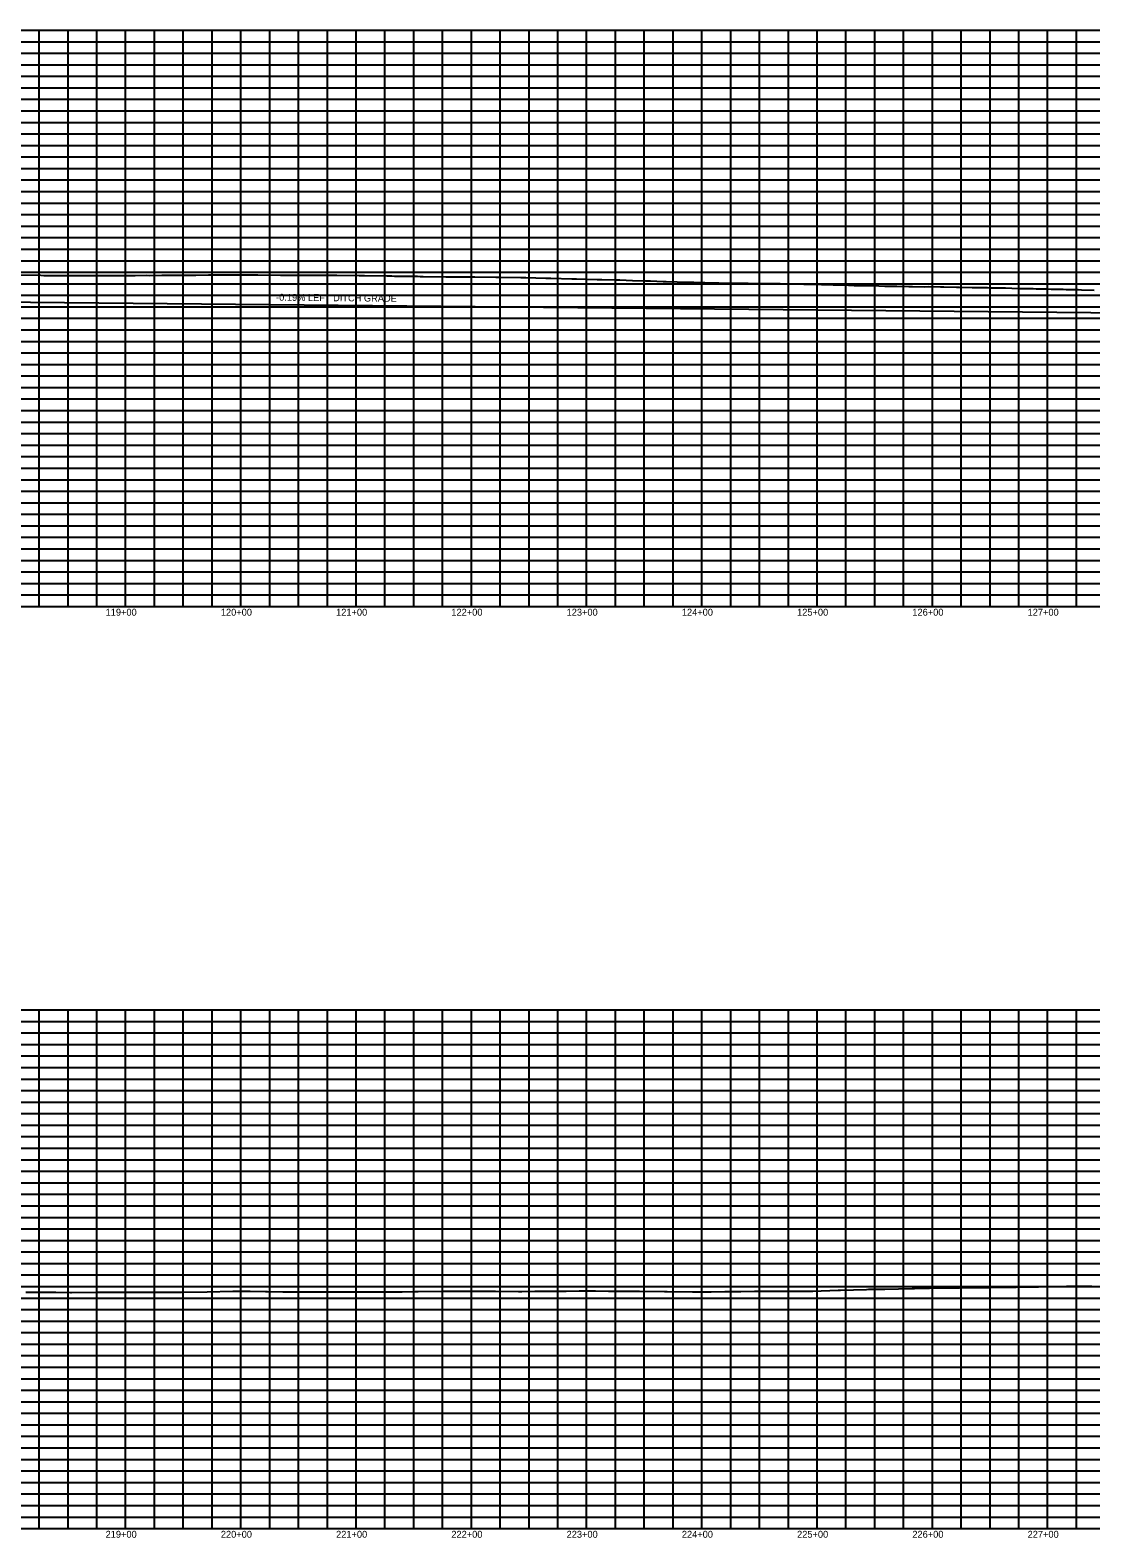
# Model space of a CAD drawing. Extents: x 1399671 to 1408349, y 1930471 to 1933387.
# Drawn here: x 1402141 to 1403062, y 1932071 to 1933379 of the extents above; entities that cross this region are included whole.
import ezdxf

# ---------------------------------------------------------------- set-up
doc = ezdxf.new("R2010")
doc.units = 0
for name, color, linetype in [('R_Exist Surface', 7, 'Continuous'), ('R_Grid', 7, 'Continuous'), ('R_Grid Annot', 7, 'Continuous'), ('R_Vert Alg', 7, 'Continuous'), ('R_Vert Alg Annot', 7, 'Continuous')]:
    doc.layers.add(name, color=color, linetype=linetype)

msp = doc.modelspace()

# ---------------------------------------------------------------- linework, layer by layer
at = {"layer": 'R_Exist Surface'}
for points in [[(1402131.6, 1933166.2), (1402150.7, 1933166.1), (1402153.1, 1933165.8), (1402164.1, 1933165.8), (1402166.5, 1933165.8), (1402177.4, 1933165.7), (1402179.8, 1933165.7), (1402190.8, 1933165.7), (1402193.2, 1933165.7), (1402195.6, 1933165.6), (1402206.5, 1933165.6), (1402216.9, 1933165.7), (1402219.5, 1933165.7), (1402229.8, 1933165.8), (1402232.4, 1933165.8), (1402242.7, 1933165.9), (1402245.3, 1933165.8), (1402255.6, 1933165.9), (1402258.2, 1933165.9), (1402269.3, 1933166), (1402271.7, 1933166), (1402282.7, 1933166.1), (1402285.1, 1933166.1), (1402296.2, 1933166.2), (1402298.6, 1933166.2), (1402309.7, 1933166.3), (1402312.1, 1933166.3), (1402314.5, 1933166.2), (1402334.1, 1933166.2), (1402336.5, 1933166.2), (1402338.8, 1933166.2), (1402358.6, 1933166.1), (1402360.9, 1933166.1), (1402380.3, 1933166), (1402384.2, 1933166.1), (1402388.4, 1933166.1), (1402407.5, 1933166), (1402426.8, 1933165.8), (1402431.3, 1933165.7), (1402450.7, 1933165.5), (1402455.1, 1933165.4), (1402457.5, 1933165.3), (1402477.4, 1933165.1), (1402479.8, 1933165), (1402482.4, 1933164.9), (1402502, 1933164.7), (1402504.6, 1933164.6), (1402522.7, 1933164.5), (1402527.2, 1933164.5), (1402545.5, 1933164.4), (1402549.8, 1933164.4), (1402567, 1933164), (1402571.5, 1933164), (1402588.7, 1933163.5), (1402593.1, 1933163.5), (1402611.2, 1933162.9), (1402615.3, 1933162.9), (1402633.4, 1933162.3), (1402637.4, 1933162.3), (1402648.6, 1933161.9), (1402652.9, 1933161.9), (1402664.1, 1933161.5), (1402675.3, 1933161), (1402679.5, 1933161), (1402690.7, 1933160.6), (1402693.1, 1933160.5), (1402712.4, 1933160), (1402714.8, 1933160), (1402717.3, 1933159.9), (1402736.4, 1933159.4), (1402738.9, 1933159.4), (1402749.4, 1933159.2), (1402753.8, 1933159.2), (1402764.3, 1933159), (1402774.7, 1933158.9), (1402779.2, 1933158.8), (1402789.6, 1933158.7), (1402792.2, 1933158.7), (1402812.6, 1933158.1), (1402815.1, 1933158.1), (1402817.7, 1933158.1), (1402838, 1933157.6), (1402840.6, 1933157.6), (1402851.5, 1933157.4), (1402856.3, 1933157.2), (1402867, 1933157), (1402877.7, 1933156.8), (1402882.9, 1933156.6), (1402893.4, 1933156.4), (1402903.9, 1933156.2), (1402907, 1933156.2), (1402917.6, 1933156), (1402920.5, 1933156.1), (1402931.3, 1933155.8), (1402934.1, 1933155.9), (1402945, 1933155.7), (1402947.6, 1933155.7), (1402958.6, 1933155.4), (1402961, 1933155.4), (1402971.9, 1933155.2), (1402974.3, 1933155.1), (1402985.3, 1933154.9), (1402987.6, 1933154.9), (1402998.6, 1933154.6), (1403001, 1933154.6), (1403011.5, 1933154.4), (1403014.1, 1933154.3), (1403024.5, 1933154.1), (1403027.2, 1933154), (1403037.6, 1933153.8), (1403040.3, 1933153.7), (1403050.6, 1933153.5), (1403053.5, 1933153.4), (1403064.5, 1933153.1)], [(1402137.7, 1932283.7), (1402150, 1932283.6), (1402162.4, 1932283.6), (1402163.6, 1932283.6), (1402176.2, 1932283.5), (1402177.3, 1932283.5), (1402199, 1932283.6), (1402200.7, 1932283.6), (1402222.6, 1932283.6), (1402224, 1932283.6), (1402247.9, 1932283.7), (1402248, 1932283.7), (1402248.1, 1932283.7), (1402249.6, 1932283.7), (1402272, 1932283.7), (1402272.7, 1932283.7), (1402295, 1932284.1), (1402317.2, 1932284.6), (1402318, 1932284.6), (1402331.5, 1932284.4), (1402332.2, 1932284.4), (1402345.5, 1932284.3), (1402346.4, 1932284.3), (1402347.4, 1932284.3), (1402360.6, 1932284.1), (1402361.8, 1932284.1), (1402374.8, 1932284), (1402376.1, 1932284), (1402398.4, 1932284), (1402399.7, 1932284), (1402401.1, 1932284), (1402423.3, 1932283.9), (1402424.6, 1932283.9), (1402435.9, 1932284), (1402438.7, 1932284), (1402450, 1932284.1), (1402461.2, 1932284.1), (1402464, 1932284.1), (1402475.3, 1932284.2), (1402478.1, 1932284.2), (1402498.9, 1932284.4), (1402501.6, 1932284.4), (1402522.5, 1932284.6), (1402542.6, 1932284.5), (1402545.2, 1932284.5), (1402565.2, 1932284.3), (1402568, 1932284.3), (1402579.3, 1932284.4), (1402580.8, 1932284.4), (1402592, 1932284.5), (1402593.5, 1932284.5), (1402604.8, 1932284.6), (1402606.3, 1932284.6), (1402617.6, 1932284.7), (1402619, 1932284.7), (1402630.4, 1932284.7), (1402631.8, 1932284.7), (1402643.2, 1932284.6), (1402644.6, 1932284.6), (1402656, 1932284.6), (1402657.4, 1932284.6), (1402668.8, 1932284.5), (1402670.1, 1932284.5), (1402691.8, 1932284.2), (1402694.2, 1932284.2), (1402716, 1932283.9), (1402718.3, 1932283.9), (1402729.9, 1932284), (1402731.1, 1932284), (1402732.3, 1932284), (1402744, 1932284.2), (1402745.1, 1932284.2), (1402756.8, 1932284.3), (1402758, 1932284.3), (1402769.7, 1932284.5), (1402770.9, 1932284.5), (1402782.4, 1932284.5), (1402783.6, 1932284.5), (1402795.1, 1932284.5), (1402803.1, 1932284.5), (1402806.5, 1932284.5), (1402807.8, 1932284.5), (1402819.2, 1932284.5), (1402820.5, 1932284.5), (1402842.5, 1932285.3), (1402844.6, 1932285.3), (1402866.9, 1932286.1), (1402868.8, 1932286.2), (1402880.8, 1932286.4), (1402882.8, 1932286.4), (1402894.7, 1932286.7), (1402906.6, 1932286.9), (1402908.7, 1932286.9), (1402920.6, 1932287.1), (1402921.7, 1932287.2), (1402933.5, 1932287.3), (1402934.7, 1932287.3), (1402946.4, 1932287.5), (1402947.7, 1932287.5), (1402959.4, 1932287.6), (1402960.7, 1932287.7), (1402972.3, 1932287.8), (1402974.7, 1932287.8), (1402994.4, 1932288), (1402996.9, 1932288.1), (1403016.4, 1932288.3), (1403037.9, 1932288.7), (1403040.5, 1932288.8), (1403062.3, 1932289.3)]]:
    msp.add_lwpolyline(points, dxfattribs=at)
at = {"layer": 'R_Grid'}
for p, q in [((1400324.2, 1933378.6), (1408224.2, 1933378.6)), ((1400324.2, 1933378.6), (1408224.2, 1933378.6)), ((1402149.2, 1932878.6), (1402149.2, 1933378.6)), ((1402174.2, 1932878.6), (1402174.2, 1933378.6)), ((1402199.2, 1932878.6), (1402199.2, 1933378.6)), ((1402224.2, 1932878.6), (1402224.2, 1933378.6)), ((1402249.2, 1932878.6), (1402249.2, 1933378.6)), ((1402274.2, 1932878.6), (1402274.2, 1933378.6)), ((1402299.2, 1932878.6), (1402299.2, 1933378.6)), ((1402324.2, 1932878.6), (1402324.2, 1933378.6)), ((1402349.2, 1932878.6), (1402349.2, 1933378.6)), ((1402374.2, 1932878.6), (1402374.2, 1933378.6)), ((1402399.2, 1932878.6), (1402399.2, 1933378.6)), ((1402424.2, 1932878.6), (1402424.2, 1933378.6)), ((1402449.2, 1932878.6), (1402449.2, 1933378.6)), ((1402474.2, 1932878.6), (1402474.2, 1933378.6)), ((1402499.2, 1932878.6), (1402499.2, 1933378.6)), ((1402524.2, 1932878.6), (1402524.2, 1933378.6)), ((1402549.2, 1932878.6), (1402549.2, 1933378.6)), ((1402574.2, 1932878.6), (1402574.2, 1933378.6)), ((1402599.2, 1932878.6), (1402599.2, 1933378.6)), ((1402624.2, 1932878.6), (1402624.2, 1933378.6)), ((1402649.2, 1932878.6), (1402649.2, 1933378.6)), ((1402674.2, 1932878.6), (1402674.2, 1933378.6)), ((1402699.2, 1932878.6), (1402699.2, 1933378.6)), ((1402724.2, 1932878.6), (1402724.2, 1933378.6)), ((1402749.2, 1932878.6), (1402749.2, 1933378.6)), ((1402774.2, 1932878.6), (1402774.2, 1933378.6)), ((1402799.2, 1932878.6), (1402799.2, 1933378.6)), ((1402824.2, 1932878.6), (1402824.2, 1933378.6)), ((1402849.2, 1932878.6), (1402849.2, 1933378.6)), ((1402874.2, 1932878.6), (1402874.2, 1933378.6)), ((1402899.2, 1932878.6), (1402899.2, 1933378.6)), ((1402924.2, 1932878.6), (1402924.2, 1933378.6)), ((1402949.2, 1932878.6), (1402949.2, 1933378.6)), ((1402974.2, 1932878.6), (1402974.2, 1933378.6)), ((1402999.2, 1932878.6), (1402999.2, 1933378.6)), ((1403024.2, 1932878.6), (1403024.2, 1933378.6)), ((1403049.2, 1932878.6), (1403049.2, 1933378.6)), ((1400324.2, 1933368.6), (1408224.2, 1933368.6)), ((1400324.2, 1933358.6), (1408224.2, 1933358.6)), ((1400324.2, 1933348.6), (1408224.2, 1933348.6)), ((1400324.2, 1933338.6), (1408224.2, 1933338.6)), ((1400324.2, 1933328.6), (1408224.2, 1933328.6)), ((1400324.2, 1933318.6), (1408224.2, 1933318.6)), ((1400324.2, 1933308.6), (1408224.2, 1933308.6)), ((1400324.2, 1933298.6), (1408224.2, 1933298.6)), ((1400324.2, 1933288.6), (1408224.2, 1933288.6)), ((1400324.2, 1933278.6), (1408224.2, 1933278.6)), ((1400324.2, 1933268.6), (1408224.2, 1933268.6)), ((1400324.2, 1933258.6), (1408224.2, 1933258.6)), ((1400324.2, 1933248.6), (1408224.2, 1933248.6)), ((1400324.2, 1933238.6), (1408224.2, 1933238.6)), ((1400324.2, 1933228.6), (1408224.2, 1933228.6)), ((1400324.2, 1933218.6), (1408224.2, 1933218.6)), ((1400324.2, 1933208.6), (1408224.2, 1933208.6)), ((1400324.2, 1933198.6), (1408224.2, 1933198.6)), ((1400324.2, 1933188.6), (1408224.2, 1933188.6)), ((1400324.2, 1933178.6), (1408224.2, 1933178.6)), ((1400324.2, 1933168.6), (1408224.2, 1933168.6)), ((1400324.2, 1933158.6), (1408224.2, 1933158.6)), ((1400324.2, 1933148.6), (1408224.2, 1933148.6)), ((1400324.2, 1933138.6), (1408224.2, 1933138.6)), ((1400324.2, 1933128.6), (1408224.2, 1933128.6)), ((1400324.2, 1933118.6), (1408224.2, 1933118.6)), ((1400324.2, 1933108.6), (1408224.2, 1933108.6)), ((1400324.2, 1933098.6), (1408224.2, 1933098.6)), ((1400324.2, 1933088.6), (1408224.2, 1933088.6)), ((1400324.2, 1933078.6), (1408224.2, 1933078.6)), ((1400324.2, 1933068.6), (1408224.2, 1933068.6)), ((1400324.2, 1933058.6), (1408224.2, 1933058.6)), ((1400324.2, 1933048.6), (1408224.2, 1933048.6)), ((1400324.2, 1933038.6), (1408224.2, 1933038.6)), ((1400324.2, 1933028.6), (1408224.2, 1933028.6)), ((1400324.2, 1933018.6), (1408224.2, 1933018.6)), ((1400324.2, 1933008.6), (1408224.2, 1933008.6)), ((1400324.2, 1932998.6), (1408224.2, 1932998.6)), ((1400324.2, 1932988.6), (1408224.2, 1932988.6)), ((1400324.2, 1932978.6), (1408224.2, 1932978.6)), ((1400324.2, 1932968.6), (1408224.2, 1932968.6)), ((1400324.2, 1932958.6), (1408224.2, 1932958.6)), ((1400324.2, 1932948.6), (1408224.2, 1932948.6)), ((1400324.2, 1932938.6), (1408224.2, 1932938.6)), ((1400324.2, 1932928.6), (1408224.2, 1932928.6)), ((1400324.2, 1932918.6), (1408224.2, 1932918.6)), ((1400324.2, 1932908.6), (1408224.2, 1932908.6)), ((1400324.2, 1932898.6), (1408224.2, 1932898.6)), ((1400324.2, 1932888.6), (1408224.2, 1932888.6)), ((1400324.2, 1932878.6), (1408224.2, 1932878.6)), ((1400324.2, 1932528.6), (1407124.2, 1932528.6)), ((1400324.2, 1932528.6), (1407124.2, 1932528.6)), ((1402149.2, 1932078.6), (1402149.2, 1932528.6)), ((1402174.2, 1932078.6), (1402174.2, 1932528.6)), ((1402199.2, 1932078.6), (1402199.2, 1932528.6)), ((1402224.2, 1932078.6), (1402224.2, 1932528.6)), ((1402249.2, 1932078.6), (1402249.2, 1932528.6)), ((1402274.2, 1932078.6), (1402274.2, 1932528.6)), ((1402299.2, 1932078.6), (1402299.2, 1932528.6)), ((1402324.2, 1932078.6), (1402324.2, 1932528.6)), ((1402349.2, 1932078.6), (1402349.2, 1932528.6)), ((1402374.2, 1932078.6), (1402374.2, 1932528.6)), ((1402399.2, 1932078.6), (1402399.2, 1932528.6)), ((1402424.2, 1932078.6), (1402424.2, 1932528.6)), ((1402449.2, 1932078.6), (1402449.2, 1932528.6)), ((1402474.2, 1932078.6), (1402474.2, 1932528.6)), ((1402499.2, 1932078.6), (1402499.2, 1932528.6)), ((1402524.2, 1932078.6), (1402524.2, 1932528.6)), ((1402549.2, 1932078.6), (1402549.2, 1932528.6)), ((1402574.2, 1932078.6), (1402574.2, 1932528.6)), ((1402599.2, 1932078.6), (1402599.2, 1932528.6)), ((1402624.2, 1932078.6), (1402624.2, 1932528.6)), ((1402649.2, 1932078.6), (1402649.2, 1932528.6)), ((1402674.2, 1932078.6), (1402674.2, 1932528.6)), ((1402699.2, 1932078.6), (1402699.2, 1932528.6)), ((1402724.2, 1932078.6), (1402724.2, 1932528.6)), ((1402749.2, 1932078.6), (1402749.2, 1932528.6)), ((1402774.2, 1932078.6), (1402774.2, 1932528.6)), ((1402799.2, 1932078.6), (1402799.2, 1932528.6)), ((1402824.2, 1932078.6), (1402824.2, 1932528.6)), ((1402849.2, 1932078.6), (1402849.2, 1932528.6)), ((1402874.2, 1932078.6), (1402874.2, 1932528.6)), ((1402899.2, 1932078.6), (1402899.2, 1932528.6)), ((1402924.2, 1932078.6), (1402924.2, 1932528.6)), ((1402949.2, 1932078.6), (1402949.2, 1932528.6)), ((1402974.2, 1932078.6), (1402974.2, 1932528.6)), ((1402999.2, 1932078.6), (1402999.2, 1932528.6)), ((1403024.2, 1932078.6), (1403024.2, 1932528.6)), ((1403049.2, 1932078.6), (1403049.2, 1932528.6)), ((1400324.2, 1932518.6), (1407124.2, 1932518.6)), ((1400324.2, 1932508.6), (1407124.2, 1932508.6)), ((1400324.2, 1932498.6), (1407124.2, 1932498.6)), ((1400324.2, 1932488.6), (1407124.2, 1932488.6)), ((1400324.2, 1932478.6), (1407124.2, 1932478.6)), ((1400324.2, 1932468.6), (1407124.2, 1932468.6)), ((1400324.2, 1932458.6), (1407124.2, 1932458.6)), ((1400324.2, 1932448.6), (1407124.2, 1932448.6)), ((1400324.2, 1932438.6), (1407124.2, 1932438.6)), ((1400324.2, 1932428.6), (1407124.2, 1932428.6)), ((1400324.2, 1932418.6), (1407124.2, 1932418.6)), ((1400324.2, 1932408.6), (1407124.2, 1932408.6)), ((1400324.2, 1932398.6), (1407124.2, 1932398.6)), ((1400324.2, 1932388.6), (1407124.2, 1932388.6)), ((1400324.2, 1932378.6), (1407124.2, 1932378.6)), ((1400324.2, 1932368.6), (1407124.2, 1932368.6)), ((1400324.2, 1932358.6), (1407124.2, 1932358.6)), ((1400324.2, 1932348.6), (1407124.2, 1932348.6)), ((1400324.2, 1932338.6), (1407124.2, 1932338.6)), ((1400324.2, 1932328.6), (1407124.2, 1932328.6)), ((1400324.2, 1932318.6), (1407124.2, 1932318.6)), ((1400324.2, 1932308.6), (1407124.2, 1932308.6)), ((1400324.2, 1932298.6), (1407124.2, 1932298.6)), ((1400324.2, 1932288.6), (1407124.2, 1932288.6)), ((1400324.2, 1932278.6), (1407124.2, 1932278.6)), ((1400324.2, 1932268.6), (1407124.2, 1932268.6)), ((1400324.2, 1932258.6), (1407124.2, 1932258.6)), ((1400324.2, 1932248.6), (1407124.2, 1932248.6)), ((1400324.2, 1932238.6), (1407124.2, 1932238.6)), ((1400324.2, 1932228.6), (1407124.2, 1932228.6)), ((1400324.2, 1932218.6), (1407124.2, 1932218.6)), ((1400324.2, 1932208.6), (1407124.2, 1932208.6)), ((1400324.2, 1932198.6), (1407124.2, 1932198.6)), ((1400324.2, 1932188.6), (1407124.2, 1932188.6)), ((1400324.2, 1932178.6), (1407124.2, 1932178.6)), ((1400324.2, 1932168.6), (1407124.2, 1932168.6)), ((1400324.2, 1932158.6), (1407124.2, 1932158.6)), ((1400324.2, 1932148.6), (1407124.2, 1932148.6)), ((1400324.2, 1932138.6), (1407124.2, 1932138.6)), ((1400324.2, 1932128.6), (1407124.2, 1932128.6)), ((1400324.2, 1932118.6), (1407124.2, 1932118.6)), ((1400324.2, 1932108.6), (1407124.2, 1932108.6)), ((1400324.2, 1932098.6), (1407124.2, 1932098.6)), ((1400324.2, 1932088.6), (1407124.2, 1932088.6)), ((1400324.2, 1932078.6), (1407124.2, 1932078.6))]:
    msp.add_line(p, q, dxfattribs=at)
at = {"layer": 'R_Vert Alg'}
msp.add_line((1401224.2, 1933151.2), (1403622.2, 1933128.4), dxfattribs=at)

# ---------------------------------------------------------------- texts
at = {"layer": 'R_Grid Annot'}
for s, p in [('119+00', (1402206.8, 1932870.6)), ('120+00', (1402306.8, 1932870.6)), ('121+00', (1402406.8, 1932870.6)), ('122+00', (1402506.8, 1932870.6)), ('123+00', (1402606.8, 1932870.6)), ('124+00', (1402706.8, 1932870.6)), ('125+00', (1402806.8, 1932870.6)), ('126+00', (1402906.8, 1932870.6)), ('127+00', (1403006.8, 1932870.6)), ('219+00', (1402206.8, 1932070.6)), ('220+00', (1402306.8, 1932070.6)), ('221+00', (1402406.8, 1932070.6)), ('222+00', (1402506.8, 1932070.6)), ('223+00', (1402606.8, 1932070.6)), ('224+00', (1402706.8, 1932070.6)), ('225+00', (1402806.8, 1932070.6)), ('226+00', (1402906.8, 1932070.6)), ('227+00', (1403006.8, 1932070.6))]:
    msp.add_text(s, height=6, dxfattribs=at).set_placement(p)
at = {"layer": 'R_Vert Alg Annot'}
msp.add_text('-0.19% LEFT DITCH GRADE', height=6, rotation=359.4553, dxfattribs=at).set_placement((1402354.7, 1933143.9))

doc.saveas('drawing.dxf')
